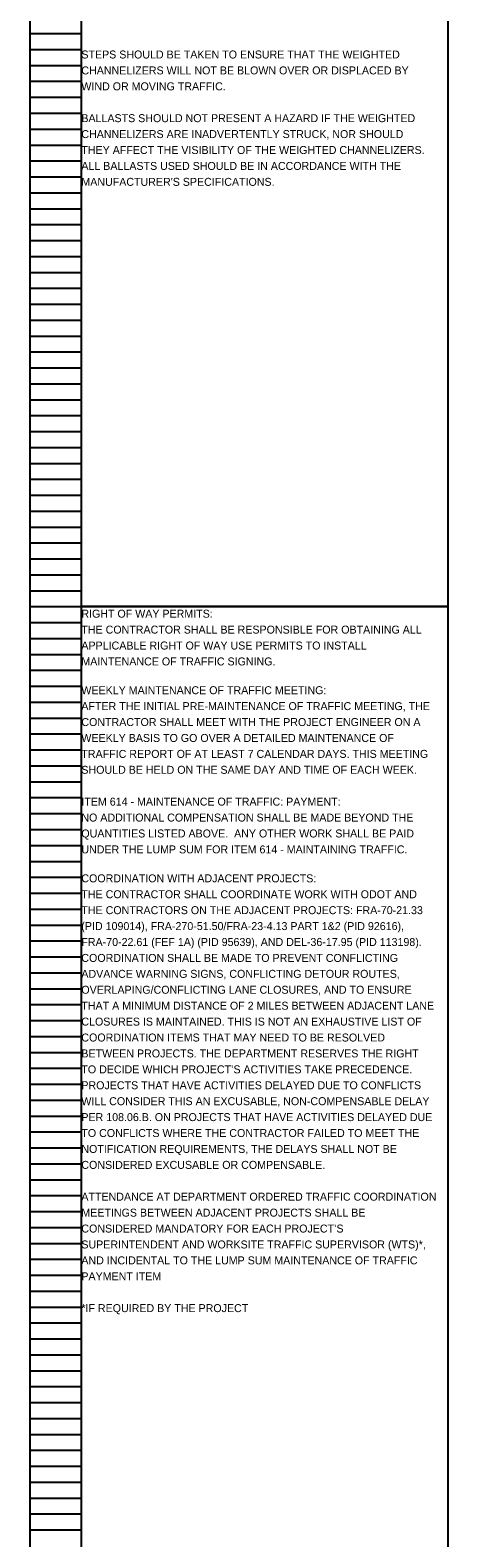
# Model space of a CAD drawing. Extents: x 16463 to 16500, y 5400 to 5823.
# Drawn here: x 16463.05 to 16470.39, y 5585.33 to 5611.85 of the extents above; entities that cross this region are included whole.
import ezdxf

# ---------------------------------------------------------------- set-up
doc = ezdxf.new("R2010")
doc.units = 0
for name, color, linetype in [('SC_Scratch1', 7, 'Continuous'), ('SH_Data', 7, 'Continuous'), ('SH_Text', 7, 'Continuous')]:
    doc.layers.add(name, color=color, linetype=linetype)

msp = doc.modelspace()

# ---------------------------------------------------------------- linework, layer by layer
at = {"layer": 'SC_Scratch1'}
for points in [[(16463.949, 5621.872), (16470.389, 5621.872), (16470.389, 5601.712), (16463.949, 5601.712)], [(16463.949, 5601.712), (16470.389, 5601.712), (16470.389, 5581.552), (16463.949, 5581.552)]]:
    msp.add_lwpolyline(points, close=True, dxfattribs=at)
at = {"layer": 'SH_Data'}
for p, q in [((16463.049, 5601.712), (16463.049, 5621.872)), ((16463.949, 5601.712), (16463.949, 5621.872)), ((16463.049, 5611.792), (16463.949, 5611.792)), ((16463.049, 5611.512), (16463.949, 5611.512)), ((16463.049, 5611.232), (16463.949, 5611.232)), ((16463.049, 5610.952), (16463.949, 5610.952)), ((16463.049, 5610.672), (16463.949, 5610.672)), ((16463.049, 5610.392), (16463.949, 5610.392)), ((16463.049, 5610.112), (16463.949, 5610.112)), ((16463.049, 5609.832), (16463.949, 5609.832)), ((16463.049, 5609.552), (16463.949, 5609.552)), ((16463.049, 5609.272), (16463.949, 5609.272)), ((16463.049, 5608.992), (16463.949, 5608.992)), ((16463.049, 5608.712), (16463.949, 5608.712)), ((16463.049, 5608.432), (16463.949, 5608.432)), ((16463.049, 5608.152), (16463.949, 5608.152)), ((16463.049, 5607.872), (16463.949, 5607.872)), ((16463.049, 5607.592), (16463.949, 5607.592)), ((16463.049, 5607.312), (16463.949, 5607.312)), ((16463.049, 5607.032), (16463.949, 5607.032)), ((16463.049, 5606.752), (16463.949, 5606.752)), ((16463.049, 5606.472), (16463.949, 5606.472)), ((16463.049, 5606.192), (16463.949, 5606.192)), ((16463.049, 5605.912), (16463.949, 5605.912)), ((16463.049, 5605.632), (16463.949, 5605.632)), ((16463.049, 5605.352), (16463.949, 5605.352)), ((16463.049, 5605.072), (16463.949, 5605.072)), ((16463.049, 5604.792), (16463.949, 5604.792)), ((16463.049, 5604.512), (16463.949, 5604.512)), ((16463.049, 5604.232), (16463.949, 5604.232)), ((16463.049, 5603.952), (16463.949, 5603.952)), ((16463.049, 5603.672), (16463.949, 5603.672)), ((16463.049, 5603.392), (16463.949, 5603.392)), ((16463.049, 5603.112), (16463.949, 5603.112)), ((16463.049, 5602.832), (16463.949, 5602.832)), ((16463.049, 5602.552), (16463.949, 5602.552)), ((16463.049, 5602.272), (16463.949, 5602.272)), ((16463.049, 5601.992), (16463.949, 5601.992)), ((16463.049, 5581.552), (16463.049, 5601.712)), ((16463.049, 5601.712), (16463.949, 5601.712)), ((16463.049, 5601.712), (16463.949, 5601.712)), ((16463.949, 5581.552), (16463.949, 5601.712)), ((16463.049, 5601.432), (16463.949, 5601.432)), ((16463.049, 5601.152), (16463.949, 5601.152)), ((16463.049, 5600.872), (16463.949, 5600.872)), ((16463.049, 5600.592), (16463.949, 5600.592)), ((16463.049, 5600.312), (16463.949, 5600.312)), ((16463.049, 5600.032), (16463.949, 5600.032)), ((16463.049, 5599.752), (16463.949, 5599.752)), ((16463.049, 5599.472), (16463.949, 5599.472)), ((16463.049, 5599.192), (16463.949, 5599.192)), ((16463.049, 5598.912), (16463.949, 5598.912)), ((16463.049, 5598.632), (16463.949, 5598.632)), ((16463.049, 5598.352), (16463.949, 5598.352)), ((16463.049, 5598.072), (16463.949, 5598.072)), ((16463.049, 5597.792), (16463.949, 5597.792)), ((16463.049, 5597.512), (16463.949, 5597.512)), ((16463.049, 5597.232), (16463.949, 5597.232)), ((16463.049, 5596.952), (16463.949, 5596.952)), ((16463.049, 5596.672), (16463.949, 5596.672)), ((16463.049, 5596.392), (16463.949, 5596.392)), ((16463.049, 5596.112), (16463.949, 5596.112)), ((16463.049, 5595.832), (16463.949, 5595.832)), ((16463.049, 5595.552), (16463.949, 5595.552)), ((16463.049, 5595.272), (16463.949, 5595.272)), ((16463.049, 5594.992), (16463.949, 5594.992)), ((16463.049, 5594.712), (16463.949, 5594.712)), ((16463.049, 5594.432), (16463.949, 5594.432)), ((16463.049, 5594.152), (16463.949, 5594.152)), ((16463.049, 5593.872), (16463.949, 5593.872)), ((16463.049, 5593.592), (16463.949, 5593.592)), ((16463.049, 5593.312), (16463.949, 5593.312)), ((16463.049, 5593.032), (16463.949, 5593.032)), ((16463.049, 5592.752), (16463.949, 5592.752)), ((16463.049, 5592.472), (16463.949, 5592.472)), ((16463.049, 5592.192), (16463.949, 5592.192)), ((16463.049, 5591.912), (16463.949, 5591.912)), ((16463.049, 5591.632), (16463.949, 5591.632)), ((16463.049, 5591.352), (16463.949, 5591.352)), ((16463.049, 5591.072), (16463.949, 5591.072)), ((16463.049, 5590.792), (16463.949, 5590.792)), ((16463.049, 5590.512), (16463.949, 5590.512)), ((16463.049, 5590.232), (16463.949, 5590.232)), ((16463.049, 5589.952), (16463.949, 5589.952)), ((16463.049, 5589.672), (16463.949, 5589.672)), ((16463.049, 5589.392), (16463.949, 5589.392)), ((16463.049, 5589.112), (16463.949, 5589.112)), ((16463.049, 5588.832), (16463.949, 5588.832)), ((16463.049, 5588.552), (16463.949, 5588.552)), ((16463.049, 5588.272), (16463.949, 5588.272)), ((16463.049, 5587.992), (16463.949, 5587.992)), ((16463.049, 5587.712), (16463.949, 5587.712)), ((16463.049, 5587.432), (16463.949, 5587.432)), ((16463.049, 5587.152), (16463.949, 5587.152)), ((16463.049, 5586.872), (16463.949, 5586.872)), ((16463.049, 5586.592), (16463.949, 5586.592)), ((16463.049, 5586.312), (16463.949, 5586.312)), ((16463.049, 5586.032), (16463.949, 5586.032)), ((16463.049, 5585.752), (16463.949, 5585.752)), ((16463.049, 5585.472), (16463.949, 5585.472))]:
    msp.add_line(p, q, dxfattribs=at)

# ---------------------------------------------------------------- texts
at = {"layer": 'SH_Text'}
for s, p in [('STEPS SHOULD BE TAKEN TO ENSURE THAT THE WEIGHTED ', (16463.949, 5611.354)), ('CHANNELIZERS WILL NOT BE BLOWN OVER OR DISPLACED BY ', (16463.949, 5611.074)), ('WIND OR MOVING TRAFFIC.  ', (16463.949, 5610.794)), ('BALLASTS SHOULD NOT PRESENT A HAZARD IF THE WEIGHTED ', (16463.949, 5610.234)), ('CHANNELIZERS ARE INADVERTENTLY STRUCK, NOR SHOULD ', (16463.949, 5609.954)), ('THEY AFFECT THE VISIBILITY OF THE WEIGHTED CHANNELIZERS.  ', (16463.949, 5609.674)), ('ALL BALLASTS USED SHOULD BE IN ACCORDANCE WITH THE ', (16463.949, 5609.394)), ("MANUFACTURER'S SPECIFICATIONS.", (16463.949, 5609.114)), ('RIGHT OF WAY PERMITS:', (16463.949, 5601.518)), ('THE CONTRACTOR SHALL BE RESPONSIBLE FOR OBTAINING ALL ', (16463.949, 5601.238)), ('APPLICABLE RIGHT OF WAY USE PERMITS TO INSTALL ', (16463.949, 5600.958)), ('MAINTENANCE OF TRAFFIC SIGNING.', (16463.949, 5600.678)), ('WEEKLY MAINTENANCE OF TRAFFIC MEETING:', (16463.949, 5600.172)), ('AFTER THE INITIAL PRE-MAINTENANCE OF TRAFFIC MEETING, THE ', (16463.949, 5599.892)), ('CONTRACTOR SHALL MEET WITH THE PROJECT ENGINEER ON A ', (16463.949, 5599.612)), ('WEEKLY BASIS TO GO OVER A DETAILED MAINTENANCE OF ', (16463.949, 5599.332)), ('TRAFFIC REPORT OF AT LEAST 7 CALENDAR DAYS. THIS MEETING ', (16463.949, 5599.052)), ('SHOULD BE HELD ON THE SAME DAY AND TIME OF EACH WEEK.', (16463.949, 5598.772)), ('ITEM 614 - MAINTENANCE OF TRAFFIC: PAYMENT:', (16463.949, 5598.212)), ('NO ADDITIONAL COMPENSATION SHALL BE MADE BEYOND THE ', (16463.949, 5597.932)), ('QUANTITIES LISTED ABOVE.  ANY OTHER WORK SHALL BE PAID ', (16463.949, 5597.652)), ('UNDER THE LUMP SUM FOR ITEM 614 - MAINTAINING TRAFFIC.', (16463.949, 5597.372)), ('COORDINATION WITH ADJACENT PROJECTS:', (16463.949, 5596.863)), ('THE CONTRACTOR SHALL COORDINATE WORK WITH ODOT AND ', (16463.949, 5596.583)), ('THE CONTRACTORS ON THE ADJACENT PROJECTS: FRA-70-21.33 ', (16463.949, 5596.303)), ('(PID 109014), FRA-270-51.50/FRA-23-4.13 PART 1&2 (PID 92616),  ', (16463.949, 5596.023)), ('FRA-70-22.61 (FEF 1A) (PID 95639), AND DEL-36-17.95 (PID 113198). ', (16463.949, 5595.743)), ('COORDINATION SHALL BE MADE TO PREVENT CONFLICTING ', (16463.949, 5595.463)), ('ADVANCE WARNING SIGNS, CONFLICTING DETOUR ROUTES, ', (16463.949, 5595.183)), ('OVERLAPING/CONFLICTING LANE CLOSURES, AND TO ENSURE ', (16463.949, 5594.903)), ('THAT A MINIMUM DISTANCE OF 2 MILES BETWEEN ADJACENT LANE ', (16463.949, 5594.623)), ('CLOSURES IS MAINTAINED. THIS IS NOT AN EXHAUSTIVE LIST OF ', (16463.949, 5594.343)), ('COORDINATION ITEMS THAT MAY NEED TO BE RESOLVED ', (16463.949, 5594.063)), ('BETWEEN PROJECTS. THE DEPARTMENT RESERVES THE RIGHT ', (16463.949, 5593.783)), ('TO DECIDE WHICH PROJECT’S ACTIVITIES TAKE PRECEDENCE. ', (16463.949, 5593.503)), ('PROJECTS THAT HAVE ACTIVITIES DELAYED DUE TO CONFLICTS ', (16463.949, 5593.223)), ('WILL CONSIDER THIS AN EXCUSABLE, NON-COMPENSABLE DELAY ', (16463.949, 5592.943)), ('PER 108.06.B. ON PROJECTS THAT HAVE ACTIVITIES DELAYED DUE ', (16463.949, 5592.663)), ('TO CONFLICTS WHERE THE CONTRACTOR FAILED TO MEET THE ', (16463.949, 5592.383)), ('NOTIFICATION REQUIREMENTS, THE DELAYS SHALL NOT BE ', (16463.949, 5592.103)), ('CONSIDERED EXCUSABLE OR COMPENSABLE.', (16463.949, 5591.823)), ('ATTENDANCE AT DEPARTMENT ORDERED TRAFFIC COORDINATION ', (16463.949, 5591.263)), ('MEETINGS BETWEEN ADJACENT PROJECTS SHALL BE ', (16463.949, 5590.983)), ('CONSIDERED MANDATORY FOR EACH PROJECT’S ', (16463.949, 5590.703)), ('SUPERINTENDENT AND WORKSITE TRAFFIC SUPERVISOR (WTS)*, ', (16463.949, 5590.423)), ('AND INCIDENTAL TO THE LUMP SUM MAINTENANCE OF TRAFFIC ', (16463.949, 5590.143)), ('PAYMENT ITEM', (16463.949, 5589.863)), ('*IF REQUIRED BY THE PROJECT', (16463.949, 5589.303))]:
    msp.add_text(s, height=0.14, dxfattribs=at).set_placement(p)

doc.saveas('drawing.dxf')
